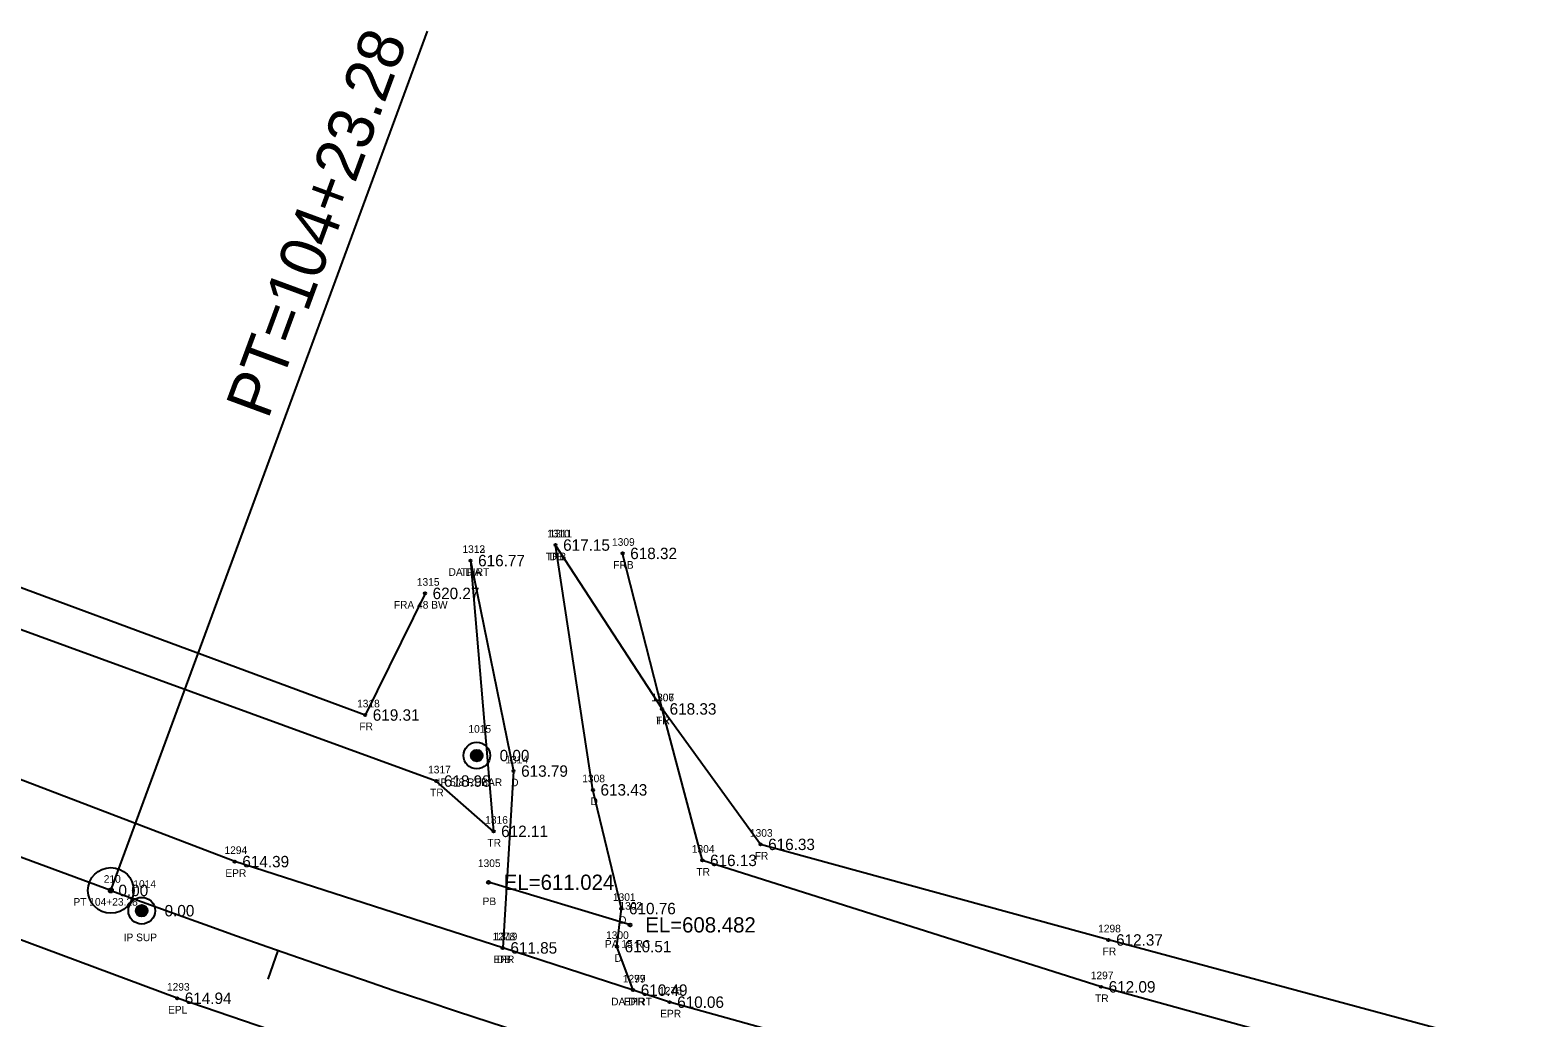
# Model space of a CAD drawing. Extents: x 1529475 to 1532053, y 876698 to 877911.
# Drawn here: x 1530226.7 to 1530424.5, y 877338.8 to 877468.4 of the extents above; entities that cross this region are included whole.
import ezdxf

# ---------------------------------------------------------------- set-up
doc = ezdxf.new("R2010")
doc.units = 0
for name, color, linetype in [('RD_EX_DR_Pipe', 7, 'Continuous'), ('RD_EX_DR_Pipe_txCode', 7, 'Continuous'), ('RD_EX_Driveway', 7, 'Continuous'), ('RD_EX_Driveway_txCode', 7, 'Continuous'), ('RD_EX_DV_Prop_txCode', 7, 'Continuous'), ('RD_EX_DV_PropPin', 7, 'Continuous'), ('RD_EX_Fence_Other', 7, 'Continuous'), ('RD_EX_Fence_Other_txCode', 7, 'Continuous'), ('RD_EX_Road', 7, 'Continuous'), ('RD_EX_Road_txCode', 7, 'Continuous'), ('RD_EX_TX_Driveway_ELEV', 7, 'Continuous'), ('RD_EX_TX_DV_Prop_ELEV', 7, 'Continuous'), ('RD_EX_TX_Fence_Other_ELEV', 7, 'Continuous'), ('RD_EX_TX_Road_ELEV', 7, 'Continuous'), ('RD_EX_TX_VEG_ELEV', 7, 'Continuous'), ('RD_EX_VEG', 7, 'Continuous'), ('RD_EX_VEG_txCode', 7, 'Continuous'), ('RD_HC_Cl', 7, 'Continuous'), ('RD_HC_Data', 7, 'Continuous'), ('RD_HC_Data_Tic', 7, 'Continuous'), ('RD_HC_Survey_ELEV', 7, 'Continuous'), ('RD_HC_txCode', 7, 'Continuous'), ('RD_SMD_Locator', 7, 'Continuous'), ('RD_TX_Pipe_ElevEX', 7, 'Continuous')]:
    doc.layers.add(name, color=color, linetype=linetype)

msp = doc.modelspace()

# ---------------------------------------------------------------- linework, layer by layer
at = {"layer": 'RD_EX_DR_Pipe'}
msp.add_line((1530305.4, 877350.97), (1530286.84, 877356.56), dxfattribs=at)
at = {"layer": 'RD_EX_Driveway'}
for points in [[(1530305.81, 877342.41), (1530303.69, 877348.12), (1530304.27, 877353.11), (1530300.53, 877368.68), (1530295.63, 877400.8)], [(1530284.48, 877398.76), (1530290.12, 877371.15), (1530288.71, 877347.95)]]:
    msp.add_lwpolyline(points, dxfattribs=at)
at = {"layer": 'RD_EX_DV_PropPin'}
for p, q in [((1530284.56, 877372.99), (1530284.56, 877373.38)), ((1530284.6, 877372.89), (1530284.6, 877373.48)), ((1530284.63, 877372.81), (1530284.63, 877373.55)), ((1530284.67, 877372.76), (1530284.67, 877373.61)), ((1530284.7, 877372.71), (1530284.7, 877373.66)), ((1530284.74, 877372.67), (1530284.74, 877373.7)), ((1530284.77, 877372.63), (1530284.77, 877373.74)), ((1530284.81, 877372.6), (1530284.81, 877373.77)), ((1530284.84, 877372.57), (1530284.84, 877373.79)), ((1530284.88, 877372.55), (1530284.88, 877373.82)), ((1530284.91, 877372.53), (1530284.91, 877373.84)), ((1530284.95, 877372.51), (1530284.95, 877373.86)), ((1530284.98, 877372.49), (1530284.98, 877373.88)), ((1530285.02, 877372.48), (1530285.02, 877373.89)), ((1530285.05, 877372.46), (1530285.05, 877373.9)), ((1530285.09, 877372.45), (1530285.09, 877373.92)), ((1530285.12, 877372.44), (1530285.12, 877373.92)), ((1530285.16, 877372.44), (1530285.16, 877373.93)), ((1530285.19, 877372.43), (1530285.19, 877373.94)), ((1530285.23, 877372.43), (1530285.23, 877373.94)), ((1530285.26, 877372.42), (1530285.26, 877373.94)), ((1530285.3, 877372.42), (1530285.3, 877373.95)), ((1530285.33, 877372.42), (1530285.33, 877373.94)), ((1530285.37, 877372.43), (1530285.37, 877373.94)), ((1530285.4, 877372.43), (1530285.4, 877373.94)), ((1530285.44, 877372.44), (1530285.44, 877373.93)), ((1530285.47, 877372.44), (1530285.47, 877373.92)), ((1530285.51, 877372.45), (1530285.51, 877373.92)), ((1530285.54, 877372.46), (1530285.54, 877373.9)), ((1530285.58, 877372.48), (1530285.58, 877373.89)), ((1530285.61, 877372.49), (1530285.61, 877373.88)), ((1530285.65, 877372.51), (1530285.65, 877373.86)), ((1530285.68, 877372.53), (1530285.68, 877373.84)), ((1530285.72, 877372.55), (1530285.72, 877373.82)), ((1530285.75, 877372.57), (1530285.75, 877373.79)), ((1530285.79, 877372.6), (1530285.79, 877373.77)), ((1530285.82, 877372.63), (1530285.82, 877373.74)), ((1530285.86, 877372.67), (1530285.86, 877373.7)), ((1530285.89, 877372.71), (1530285.89, 877373.66)), ((1530285.93, 877372.76), (1530285.93, 877373.61)), ((1530285.96, 877372.81), (1530285.96, 877373.55)), ((1530286, 877372.89), (1530286, 877373.48)), ((1530286.03, 877372.99), (1530286.03, 877373.38)), ((1530240.62, 877352.63), (1530240.62, 877353.03)), ((1530240.65, 877352.53), (1530240.65, 877353.13)), ((1530240.69, 877352.46), (1530240.69, 877353.2)), ((1530240.72, 877352.4), (1530240.72, 877353.26)), ((1530240.76, 877352.36), (1530240.76, 877353.3)), ((1530240.79, 877352.32), (1530240.79, 877353.35)), ((1530240.83, 877352.28), (1530240.83, 877353.38)), ((1530240.86, 877352.25), (1530240.86, 877353.41)), ((1530240.9, 877352.22), (1530240.9, 877353.44)), ((1530240.93, 877352.2), (1530240.93, 877353.47)), ((1530240.97, 877352.17), (1530240.97, 877353.49)), ((1530241, 877352.15), (1530241, 877353.51)), ((1530241.04, 877352.14), (1530241.04, 877353.52)), ((1530241.07, 877352.12), (1530241.07, 877353.54)), ((1530241.11, 877352.11), (1530241.11, 877353.55)), ((1530241.14, 877352.1), (1530241.14, 877353.56)), ((1530241.18, 877352.09), (1530241.18, 877353.57)), ((1530241.21, 877352.08), (1530241.21, 877353.58)), ((1530241.25, 877352.08), (1530241.25, 877353.58)), ((1530241.28, 877352.07), (1530241.28, 877353.59)), ((1530241.32, 877352.07), (1530241.32, 877353.59)), ((1530241.35, 877352.07), (1530241.35, 877353.59)), ((1530241.39, 877352.07), (1530241.39, 877353.59)), ((1530241.42, 877352.07), (1530241.42, 877353.59)), ((1530241.46, 877352.08), (1530241.46, 877353.58)), ((1530241.49, 877352.08), (1530241.49, 877353.58)), ((1530241.53, 877352.09), (1530241.53, 877353.57)), ((1530241.56, 877352.1), (1530241.56, 877353.56)), ((1530241.6, 877352.11), (1530241.6, 877353.55)), ((1530241.63, 877352.12), (1530241.63, 877353.54)), ((1530241.67, 877352.14), (1530241.67, 877353.52)), ((1530241.7, 877352.15), (1530241.7, 877353.51)), ((1530241.74, 877352.17), (1530241.74, 877353.49)), ((1530241.77, 877352.2), (1530241.77, 877353.47)), ((1530241.81, 877352.22), (1530241.81, 877353.44)), ((1530241.84, 877352.25), (1530241.84, 877353.41)), ((1530241.88, 877352.28), (1530241.88, 877353.38)), ((1530241.91, 877352.32), (1530241.91, 877353.35)), ((1530241.95, 877352.36), (1530241.95, 877353.3)), ((1530241.98, 877352.4), (1530241.98, 877353.26)), ((1530242.02, 877352.46), (1530242.02, 877353.2)), ((1530242.05, 877352.53), (1530242.05, 877353.13)), ((1530242.09, 877352.63), (1530242.09, 877353.03))]:
    msp.add_line(p, q, dxfattribs=at)
for centre, radius in [((1530285.3, 877373.18), 1.75), ((1530285.3, 877373.18), 0.761), ((1530241.35, 877352.83), 1.75), ((1530241.35, 877352.83), 0.761)]:
    msp.add_circle(centre, radius, dxfattribs=at)
at = {"layer": 'RD_EX_Fence_Other'}
for points in [[(1530278.51, 877394.46), (1530270.66, 877378.5), (1530200.44, 877404.47)], [(1530811.24, 877377.37), (1530859.11, 877317.26), (1530840.03, 877318.28), (1530790.63, 877336.24), (1530780.69, 877332.06), (1530773.35, 877330.36), (1530778.53, 877311.65), (1530751.94, 877310.84), (1530704.94, 877310.7), (1530603.15, 877311.86), (1530564.36, 877314.35), (1530514.23, 877318.81), (1530479.67, 877321.7), (1530413.71, 877336.7), (1530368.16, 877348.99), (1530322.52, 877361.53), (1530309.6, 877379.3), (1530304.43, 877399.7)]]:
    msp.add_lwpolyline(points, dxfattribs=at)
at = {"layer": 'RD_EX_Road'}
for points in [[(1530865.35, 877283.66), (1530865.36, 877280.61), (1530815.01, 877277.89), (1530763.54, 877277.33), (1530711.24, 877277.01), (1530660.64, 877277.93), (1530609.51, 877281.74), (1530559.88, 877286.96), (1530511.03, 877294.4), (1530460.35, 877303.35), (1530410.49, 877314.53), (1530361.04, 877326.77), (1530310.59, 877340.83), (1530305.81, 877342.41), (1530288.71, 877347.95), (1530253.55, 877359.27), (1530192.32, 877382.67)], [(1530866.41, 877261.44), (1530852.87, 877260.97), (1530806.23, 877259.4), (1530762.44, 877259.05), (1530711.8, 877259.77), (1530659.89, 877260.87), (1530608.32, 877263.5), (1530557.85, 877268.33), (1530507.29, 877275.71), (1530456.72, 877284.51), (1530406.3, 877294.52), (1530356.75, 877305.76), (1530307.05, 877320.51), (1530246, 877341.34), (1530185.26, 877363.97)]]:
    msp.add_lwpolyline(points, dxfattribs=at)
at = {"layer": 'RD_EX_VEG'}
for points in [[(1530772.69, 877331.81), (1530751.94, 877310.84), (1530704.94, 877310.7), (1530664.32, 877301.01), (1530564.36, 877314.35), (1530547.76, 877305.07), (1530463.97, 877318.83), (1530412.7, 877330.28), (1530367.19, 877342.84), (1530314.9, 877359.43), (1530309.6, 877379.3), (1530295.63, 877400.8)], [(1530284.48, 877398.76), (1530287.5, 877363.24), (1530279.98, 877369.84), (1530199.35, 877399.19)]]:
    msp.add_lwpolyline(points, dxfattribs=at)
at = {"layer": 'RD_HC_Cl'}
msp.add_line((1530237.3, 877355.49), (1530031.92, 877431.15), dxfattribs=at)
msp.add_arc((1530728.17, 878687.95), 1420, 249.7768, 272.33207, dxfattribs=at)
at = {"layer": 'RD_HC_Data'}
msp.add_line((1530237.3, 877355.49), (1530278.83, 877468.21), dxfattribs=at)
for radius in [3, 0.282]:
    msp.add_circle((1530237.3, 877355.49), radius, dxfattribs=at)
at = {"layer": 'RD_HC_Data_Tic'}
msp.add_line((1530259.21, 877347.62), (1530257.89, 877343.85), dxfattribs=at)
at = {"layer": 'RD_SMD_Locator'}
for centre, radius in [((1530295.63, 877400.8), 0.15), ((1530295.63, 877400.8), 0.15), ((1530284.48, 877398.76), 0.15), ((1530284.48, 877398.76), 0.15), ((1530304.43, 877399.7), 0.15), ((1530278.51, 877394.46), 0.15), ((1530270.66, 877378.5), 0.15), ((1530309.6, 877379.3), 0.15), ((1530309.6, 877379.3), 0.15), ((1530285.3, 877373.18), 0.15), ((1530290.12, 877371.15), 0.15), ((1530279.98, 877369.84), 0.15), ((1530300.53, 877368.68), 0.15), ((1530287.5, 877363.24), 0.15), ((1530322.52, 877361.53), 0.15), ((1530253.55, 877359.27), 0.15), ((1530314.9, 877359.43), 0.15), ((1530286.84, 877356.56), 0.2), ((1530237.3, 877355.49), 0.15), ((1530241.35, 877352.83), 0.15), ((1530304.27, 877353.11), 0.15), ((1530305.4, 877350.97), 0.2), ((1530368.16, 877348.99), 0.15), ((1530288.71, 877347.95), 0.15), ((1530288.71, 877347.95), 0.15), ((1530303.69, 877348.12), 0.15), ((1530367.19, 877342.84), 0.15), ((1530246, 877341.34), 0.15), ((1530305.81, 877342.41), 0.15), ((1530305.81, 877342.41), 0.15), ((1530310.59, 877340.83), 0.15)]:
    msp.add_circle(centre, radius, dxfattribs=at)

# ---------------------------------------------------------------- texts
at = {"layer": 'RD_EX_DR_Pipe_txCode'}
for s, p in [('1305', (1530285.45, 877358.56)), ('PB', (1530286.06, 877353.56)), ('1302', (1530304.01, 877352.97)), ('PA 15 RC', (1530302.11, 877347.97))]:
    msp.add_text(s, height=1, dxfattribs=at).set_placement(p)
at = {"layer": 'RD_EX_Driveway_txCode'}
for s, p in [('1310', (1530294.53, 877401.8)), ('1313', (1530283.42, 877399.76)), ('DB', (1530294.85, 877398.8)), ('DA DIRT', (1530281.6, 877396.76)), ('1314', (1530289.05, 877372.15)), ('1308', (1530299.14, 877369.68)), ('D', (1530289.81, 877369.15)), ('D', (1530300.22, 877366.68)), ('1301', (1530303.16, 877354.11)), ('D', (1530303.96, 877351.11)), ('1319', (1530287.65, 877348.95)), ('1300', (1530302.26, 877349.12)), ('DB', (1530287.93, 877345.95)), ('D', (1530303.38, 877346.12)), ('1299', (1530304.46, 877343.41)), ('DA DIRT', (1530302.93, 877340.41))]:
    msp.add_text(s, height=1, dxfattribs=at).set_placement(p)
at = {"layer": 'RD_EX_DV_Prop_txCode'}
for s, p in [('1015', (1530284.2, 877376.18)), ('IP 5/8 REBAR', (1530280.16, 877369.18)), ('1014', (1530240.25, 877355.83)), ('IP SUP', (1530238.98, 877348.83))]:
    msp.add_text(s, height=1, dxfattribs=at).set_placement(p)
at = {"layer": 'RD_EX_Fence_Other_txCode'}
for s, p in [('1309', (1530303.04, 877400.7)), ('FRB', (1530303.2, 877397.7)), ('1315', (1530277.44, 877395.46)), ('FRA 48 BW', (1530274.42, 877392.46)), ('1318', (1530269.6, 877379.5)), ('1306', (1530308.2, 877380.3)), ('FR', (1530308.85, 877377.3)), ('FR', (1530269.9, 877376.5)), ('1303', (1530321.13, 877362.53)), ('FR', (1530321.76, 877359.53)), ('1298', (1530366.81, 877349.99)), ('FR', (1530367.4, 877346.99))]:
    msp.add_text(s, height=1, dxfattribs=at).set_placement(p)
at = {"layer": 'RD_EX_Road_txCode'}
for s, p in [('1294', (1530252.21, 877360.27)), ('EPR', (1530252.32, 877357.27)), ('1278', (1530287.37, 877348.95)), ('EPR', (1530287.48, 877345.95)), ('1293', (1530244.66, 877342.34)), ('1277', (1530304.46, 877343.41)), ('1276', (1530309.22, 877341.83)), ('EPR', (1530304.58, 877340.41)), ('EPL', (1530244.8, 877339.34)), ('EPR', (1530309.36, 877338.83))]:
    msp.add_text(s, height=1, dxfattribs=at).set_placement(p)
at = {"layer": 'RD_EX_TX_Driveway_ELEV'}
for s, p in [('617.15', (1530296.63, 877400.05)), ('616.77', (1530285.48, 877398.01)), ('613.79', (1530291.12, 877370.4)), ('613.43', (1530301.53, 877367.93)), ('610.76', (1530305.27, 877352.36)), ('611.85', (1530289.71, 877347.2)), ('610.51', (1530304.69, 877347.37)), ('610.49', (1530306.81, 877341.66))]:
    msp.add_text(s, height=1.5, dxfattribs=at).set_placement(p)
at = {"layer": 'RD_EX_TX_DV_Prop_ELEV'}
for p in [(1530288.3, 877372.43), (1530244.35, 877352.08)]:
    msp.add_text('0.00', height=1.5, dxfattribs=at).set_placement(p)
at = {"layer": 'RD_EX_TX_Fence_Other_ELEV'}
for s, p in [('618.32', (1530305.43, 877398.95)), ('620.27', (1530279.51, 877393.71)), ('619.31', (1530271.66, 877377.75)), ('618.33', (1530310.6, 877378.55)), ('616.33', (1530323.52, 877360.78)), ('612.37', (1530369.16, 877348.24))]:
    msp.add_text(s, height=1.5, dxfattribs=at).set_placement(p)
at = {"layer": 'RD_EX_TX_Road_ELEV'}
for s, p in [('614.39', (1530254.55, 877358.52)), ('611.85', (1530289.71, 877347.2)), ('610.49', (1530306.81, 877341.66)), ('614.94', (1530247, 877340.59)), ('610.06', (1530311.59, 877340.08))]:
    msp.add_text(s, height=1.5, dxfattribs=at).set_placement(p)
at = {"layer": 'RD_EX_TX_VEG_ELEV'}
for s, p in [('617.15', (1530296.63, 877400.05)), ('616.77', (1530285.48, 877398.01)), ('618.33', (1530310.6, 877378.55)), ('618.98', (1530280.98, 877369.09)), ('612.11', (1530288.5, 877362.49)), ('616.13', (1530315.9, 877358.68)), ('612.09', (1530368.19, 877342.09))]:
    msp.add_text(s, height=1.5, dxfattribs=at).set_placement(p)
at = {"layer": 'RD_EX_VEG_txCode'}
for s, p in [('1311', (1530294.85, 877401.8)), ('1312', (1530283.42, 877399.76)), ('TRB', (1530294.36, 877398.8)), ('TRA', (1530283.2, 877396.76)), ('1307', (1530308.22, 877380.3)), ('TR', (1530308.81, 877377.3)), ('1317', (1530278.91, 877370.84)), ('TR', (1530279.18, 877367.84)), ('1316', (1530286.41, 877364.24)), ('TR', (1530286.7, 877361.24)), ('1304', (1530313.51, 877360.43)), ('TR', (1530314.11, 877357.43)), ('1297', (1530365.84, 877343.84)), ('TR', (1530366.4, 877340.84))]:
    msp.add_text(s, height=1, dxfattribs=at).set_placement(p)
at = {"layer": 'RD_HC_Data'}
msp.add_text('PT=104+23.28', height=6, rotation=69.7768, dxfattribs=at).set_placement((1530257.9, 877417.17))
at = {"layer": 'RD_HC_Survey_ELEV'}
msp.add_text('0.00', height=1.5, dxfattribs=at).set_placement((1530238.3, 877354.74))
at = {"layer": 'RD_HC_txCode'}
for s, p in [('210', (1530236.37, 877356.49)), ('PT 104+23.28', (1530232.39, 877353.49))]:
    msp.add_text(s, height=1, dxfattribs=at).set_placement(p)
at = {"layer": 'RD_TX_Pipe_ElevEX'}
for s, p in [('EL=611.024', (1530288.84, 877355.56)), ('EL=608.482', (1530307.4, 877349.97))]:
    msp.add_text(s, height=2, dxfattribs=at).set_placement(p)

doc.saveas('drawing.dxf')
